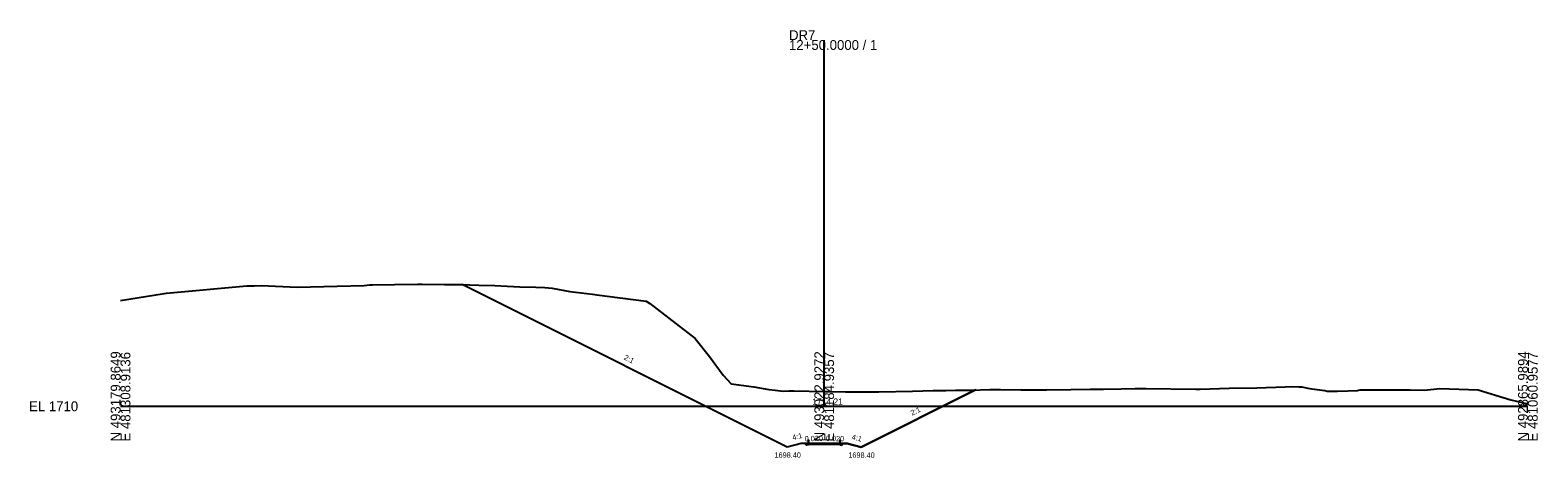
# Model space of a CAD drawing. Extents: x -26 to 403, y -10 to 4215.
# Drawn here: x -25.7 to 402.8, y 2485.4 to 2606.7 of the extents above; entities that cross this region are included whole.
import ezdxf

# ---------------------------------------------------------------- set-up
doc = ezdxf.new("R2010")
doc.units = 0
for name, color, linetype in [('Exist Cross Section Cell', 7, 'Continuous'), ('Exist XS Center Line Elevation Label', 7, 'Continuous'), ('Exist XS Ground Line', 7, 'Continuous'), ('Prop XS Ditch Slope Text', 7, 'Continuous'), ('Prop XS Ditch Standard Text', 7, 'Continuous'), ('Prop XS Dump Level', 7, 'Continuous'), ('Prop XS Earthwork Shape', 7, 'Continuous'), ('Prop XS EOT Tick Mark', 7, 'Continuous'), ('Prop XS Finish Grade', 7, 'Continuous'), ('Prop XS Finish Grade Earthwork', 7, 'Continuous'), ('Prop XS Finish Grade Pavement', 7, 'Continuous'), ('Prop XS Hydro Typical Ditch Data', 7, 'Continuous'), ('Prop XS Pvmt Edge Slope', 7, 'Continuous'), ('Prop XS SE Text', 7, 'Continuous'), ('Prop XS Shoulder Borrow Shape', 7, 'Continuous'), ('Prop XS Side Slope Text', 7, 'Continuous'), ('Prop XS Subgrade Earthwork', 7, 'Continuous')]:
    doc.layers.add(name, color=color, linetype=linetype)

msp = doc.modelspace()

# ---------------------------------------------------------------- linework, layer by layer
at = {"layer": 'Exist Cross Section Cell'}
for p, q in [((200, 2500), (200, 2603.93)), ((0, 2500), (200, 2500)), ((200, 2500), (400, 2500))]:
    msp.add_line(p, q, dxfattribs=at)
at = {"layer": 'Exist XS Ground Line'}
msp.add_lwpolyline([(0, 2530.03), (12.39, 2532.02), (13.05, 2532.12), (35.86, 2534.18), (37.97, 2534.22), (40, 2534.32), (50.19, 2533.76), (57.74, 2533.98), (69.27, 2534.31), (70.75, 2534.49), (71.65, 2534.49), (77.87, 2534.57), (84.4, 2534.64), (84.99, 2534.63), (85.74, 2534.64), (92.11, 2534.57), (97.14, 2534.59), (99.23, 2534.47), (101.87, 2534.36), (106.35, 2534.26), (109.89, 2534.07), (113.47, 2533.88), (118.01, 2533.83), (120.59, 2533.74), (122.64, 2533.51), (127.71, 2532.61), (134.14, 2531.8), (134.84, 2531.74), (135.38, 2531.67), (142.04, 2530.8), (149.44, 2529.8), (150.42, 2529.14), (163.32, 2519.22), (167.36, 2514.09), (171.29, 2508.86), (173.51, 2506.38), (180.04, 2505.54), (184.28, 2504.8), (186.03, 2504.6), (188.29, 2504.27), (189.95, 2504.35), (191.38, 2504.34), (200, 2504.21), (201.42, 2504.19), (206.1, 2504.11), (207.72, 2504.11), (209.39, 2504.11), (210.34, 2504.11), (215.57, 2504.09), (225.13, 2504.33), (230.95, 2504.51), (234.53, 2504.51), (237.35, 2504.54), (241.65, 2504.59), (247.09, 2504.75), (248.77, 2504.78), (250.1, 2504.77), (255.89, 2504.67), (263.22, 2504.68), (270.13, 2504.75), (275.59, 2504.81), (277.25, 2504.84), (279.36, 2504.87), (284.38, 2504.95), (288.34, 2505.01), (291.5, 2505.07), (305.62, 2504.82), (305.96, 2504.82), (306.9, 2504.83), (315.12, 2505.16), (322.99, 2505.27), (331.03, 2505.54), (332.84, 2505.59), (334.89, 2505.52), (335.44, 2505.52), (335.75, 2505.49), (337.43, 2505.13), (338.57, 2504.97), (342.34, 2504.45), (342.98, 2504.32), (345.9, 2504.27), (348.85, 2504.35), (351.6, 2504.52), (352.34, 2504.62), (366.58, 2504.66), (370.65, 2504.6), (374.99, 2505.03), (385.84, 2504.69), (390.85, 2503.14), (395.15, 2501.84), (400, 2500.7)], dxfattribs=at)
at = {"layer": 'Prop XS Dump Level'}
for p, q in [((195.5, 2489.56), (200, 2489.65)), ((200, 2489.65), (204.5, 2489.56))]:
    msp.add_line(p, q, dxfattribs=at)
at = {"layer": 'Prop XS Earthwork Shape'}
msp.add_lwpolyline([(189.5, 2488.4), (97.12, 2534.59), (97.14, 2534.59), (99.23, 2534.47), (101.87, 2534.36), (106.35, 2534.26), (109.89, 2534.07), (113.47, 2533.88), (118.01, 2533.83), (120.59, 2533.74), (122.64, 2533.51), (127.71, 2532.61), (134.14, 2531.8), (134.84, 2531.74), (135.38, 2531.67), (142.04, 2530.8), (149.44, 2529.8), (150.42, 2529.14), (163.32, 2519.22), (167.36, 2514.09), (171.29, 2508.86), (173.51, 2506.38), (180.04, 2505.54), (184.28, 2504.8), (186.03, 2504.6), (188.29, 2504.27), (189.95, 2504.35), (191.38, 2504.34), (200, 2504.21), (201.42, 2504.19), (206.1, 2504.11), (207.72, 2504.11), (209.39, 2504.11), (210.34, 2504.11), (215.57, 2504.09), (225.13, 2504.33), (230.95, 2504.51), (234.53, 2504.51), (237.35, 2504.54), (241.65, 2504.59), (242.96, 2504.63), (210.5, 2488.4), (206.5, 2489.4), (205.52, 2489.48), (205.05, 2489), (204.5, 2489.02), (200, 2489.11), (195.5, 2489.02), (194.95, 2489), (194.48, 2489.48), (193.5, 2489.4)], close=True, dxfattribs=at)
at = {"layer": 'Prop XS EOT Tick Mark'}
for p, q in [((195.5, 2489.56), (195.5, 2490.56)), ((204.5, 2489.56), (204.5, 2490.56))]:
    msp.add_line(p, q, dxfattribs=at)
at = {"layer": 'Prop XS Finish Grade'}
for p, q in [((195.5, 2489.56), (194.48, 2489.48)), ((204.5, 2489.56), (205.52, 2489.48))]:
    msp.add_line(p, q, dxfattribs=at)
at = {"layer": 'Prop XS Finish Grade Earthwork'}
for p, q in [((189.5, 2488.4), (97.12, 2534.59)), ((210.5, 2488.4), (242.96, 2504.63)), ((193.5, 2489.4), (189.5, 2488.4)), ((194.48, 2489.48), (193.5, 2489.4)), ((205.52, 2489.48), (206.5, 2489.4)), ((206.5, 2489.4), (210.5, 2488.4))]:
    msp.add_line(p, q, dxfattribs=at)
at = {"layer": 'Prop XS Finish Grade Pavement'}
for p, q in [((195.5, 2489.56), (200, 2489.65)), ((200, 2489.65), (204.5, 2489.56))]:
    msp.add_line(p, q, dxfattribs=at)
at = {"layer": 'Prop XS Hydro Typical Ditch Data'}
for p, q in [((189.5, 2488.4), (97.12, 2534.59)), ((210.5, 2488.4), (242.96, 2504.63)), ((193.5, 2489.4), (189.5, 2488.4)), ((206.5, 2489.4), (210.5, 2488.4))]:
    msp.add_line(p, q, dxfattribs=at)
at = {"layer": 'Prop XS Pvmt Edge Slope'}
for p, q in [((195.5, 2489.56), (194.95, 2489)), ((204.5, 2489.56), (205.05, 2489))]:
    msp.add_line(p, q, dxfattribs=at)
at = {"layer": 'Prop XS Shoulder Borrow Shape'}
for points in [[(195.5, 2489.56), (194.95, 2489), (194.48, 2489.48)], [(195.5, 2489.56), (194.95, 2489), (194.48, 2489.48)], [(205.05, 2489), (205.52, 2489.48), (204.5, 2489.56)], [(205.05, 2489), (205.52, 2489.48), (204.5, 2489.56)]]:
    msp.add_lwpolyline(points, close=True, dxfattribs=at)
at = {"layer": 'Prop XS Subgrade Earthwork'}
for p, q in [((194.95, 2489), (194.48, 2489.48)), ((195.5, 2489.02), (194.95, 2489)), ((200, 2489.11), (195.5, 2489.02)), ((204.5, 2489.02), (200, 2489.11)), ((204.5, 2489.02), (205.05, 2489)), ((205.05, 2489), (205.52, 2489.48))]:
    msp.add_line(p, q, dxfattribs=at)

# ---------------------------------------------------------------- texts
at = {"layer": 'Exist Cross Section Cell'}
for s, p in [('DR7', (190, 2603.93)), ('12+50.0000 / 1', (190, 2601.13)), ('EL 1710', (-26, 2498.6))]:
    msp.add_text(s, height=2.8, dxfattribs=at).set_placement(p)
for s, p in [('N 492865.9894', (400, 2490)), ('N 493179.8649', (0, 2490)), ('E 481308.9136', (2.8, 2490)), ('N 493022.9272', (200, 2490)), ('E 481184.9357', (202.8, 2490)), ('E 481060.9577', (402.8, 2490))]:
    msp.add_text(s, height=2.8, rotation=90, dxfattribs=at).set_placement(p)
at = {"layer": 'Exist XS Center Line Elevation Label'}
msp.add_text('1714.21', height=1.8, dxfattribs=at).set_placement((196.6, 2500.41))
at = {"layer": 'Prop XS Ditch Slope Text'}
for rotation, p in [(14.0362, (191.14, 2490.35)), (345.9638, (207.71, 2490.64))]:
    msp.add_text('4:1', height=1.5, rotation=rotation, dxfattribs=at).set_placement(p)
at = {"layer": 'Prop XS Ditch Standard Text'}
for p in [(185.87, 2485.4), (206.87, 2485.4)]:
    msp.add_text('1698.40', height=1.5, dxfattribs=at).set_placement(p)
at = {"layer": 'Prop XS Dump Level'}
for p in [(193.5, 2489.36), (206.5, 2489.36)]:
    msp.add_text('Case1', height=0.04, dxfattribs=at).set_placement(p)
at = {"layer": 'Prop XS SE Text'}
for rotation, p in [(1.1458, (194.47, 2490.05)), (358.8542, (200.48, 2490.15))]:
    msp.add_text('0.020', height=1.5, rotation=rotation, dxfattribs=at).set_placement(p)
at = {"layer": 'Prop XS Side Slope Text'}
for rotation, p in [(333.4349, (142.92, 2513.37)), (26.5651, (224.99, 2497.32))]:
    msp.add_text('2:1', height=1.5, rotation=rotation, dxfattribs=at).set_placement(p)

doc.saveas('drawing.dxf')
